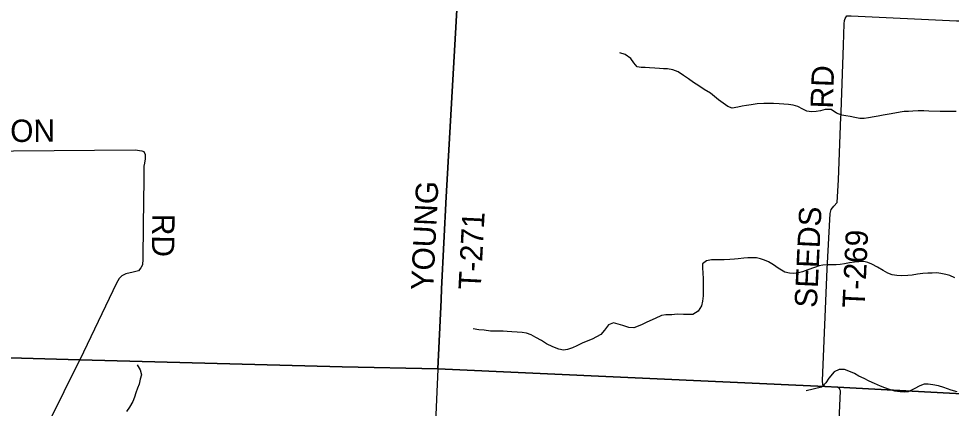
# Model space of a CAD drawing. Extents: x 114843 to 284848, y 317643 to 566895.
# Drawn here: x 166732 to 179255, y 330149 to 335383 of the extents above; entities that cross this region are included whole.
import ezdxf

# ---------------------------------------------------------------- set-up
doc = ezdxf.new("R2010")
doc.units = 0
for name, color, linetype in [('GM_X_County', 7, 'Continuous'), ('GM_X_Minor_River', 7, 'Continuous'), ('GM_X_Township', 7, 'Continuous'), ('GM_X_Township_Road', 7, 'Continuous'), ('GM_X_Township_Road_Text', 7, 'Continuous')]:
    doc.layers.add(name, color=color, linetype=linetype)

msp = doc.modelspace()

# ---------------------------------------------------------------- linework, layer by layer
at = {"layer": 'GM_X_County'}
for points in [[(181070, 330253), (177726, 330436), (177559, 330442), (172361, 330680), (171077, 330708), (167555, 330803), (166612, 330827), (164830, 330872), (164629, 330877), (164246, 330887), (163636, 330895), (163102, 330903), (159721, 330984), (157886, 331029), (151589, 331336), (151481, 331341), (151397, 331346), (149710, 331439), (149297, 331469), (137728, 332419)], [(137728, 332419), (149297, 331469), (149710, 331439), (151397, 331346), (151481, 331341), (151589, 331336), (157886, 331029), (159721, 330984), (163102, 330903), (163636, 330895), (164246, 330887), (164629, 330877), (164830, 330872), (166612, 330827), (167555, 330803), (171077, 330708), (172361, 330680), (177559, 330442), (177726, 330436), (181070, 330253)]]:
    msp.add_lwpolyline(points, dxfattribs=at)
at = {"layer": 'GM_X_Minor_River'}
for points in [[(176448, 334207), (176388, 334193), (176312, 334179), (176256, 334203), (176192, 334247), (176130, 334291), (176074, 334338), (176020, 334380), (175938, 334432), (175866, 334480), (175794, 334526), (175728, 334573), (175660, 334619), (175588, 334669), (175518, 334695), (175446, 334707), (175392, 334709), (175338, 334713), (175274, 334716), (175204, 334722), (175146, 334726), (175092, 334726), (175038, 334738), (174992, 334788), (174950, 334846), (174876, 334901), (174806, 334923)], [(179318, 334137), (179230, 334135), (179180, 334137), (179104, 334137), (178952, 334141), (178884, 334145), (178810, 334145), (178738, 334141), (178678, 334138), (178621, 334134), (178569, 334126), (178497, 334112), (178421, 334098), (178339, 334086), (178271, 334074), (178217, 334066), (178143, 334052), (178083, 334044), (178027, 334040), (177961, 334054), (177899, 334068), (177839, 334077), (177783, 334085), (177713, 334115), (177641, 334161), (177563, 334161), (177499, 334145), (177441, 334135), (177377, 334133), (177317, 334141), (177261, 334168), (177193, 334204), (177133, 334222), (177067, 334230), (177005, 334236), (176942, 334240), (176868, 334242), (176802, 334244), (176736, 334244), (176646, 334239), (176568, 334227), (176504, 334217), (176448, 334207)], [(179300, 331901), (179236, 331933), (179182, 331949), (179116, 331962), (179062, 331968), (178996, 331966), (178938, 331964), (178872, 331960), (178800, 331950), (178728, 331940), (178672, 331934), (178588, 331930), (178522, 331932), (178460, 331942), (178402, 331965), (178342, 331999), (178264, 332045), (178188, 332085), (178132, 332109), (178080, 332121), (178012, 332119), (177954, 332114), (177890, 332102), (177822, 332090), (177764, 332082), (177709, 332076), (177643, 332076), (177583, 332078), (177531, 332074), (177479, 332064), (177419, 332042), (177329, 332008), (177255, 331984), (177185, 331966), (177135, 331962), (177081, 331964), (177019, 331980), (176929, 332033), (176867, 332075), (176799, 332117), (176747, 332139), (176693, 332159), (176639, 332169), (176585, 332172), (176523, 332170), (176469, 332166), (176395, 332158), (176345, 332152), (176281, 332148), (176203, 332142), (176147, 332144), (176088, 332146), (176036, 332142), (175966, 332130), (175916, 332092), (175914, 332030), (175918, 331968), (175922, 331890), (175924, 331820), (175922, 331737), (175922, 331661), (175913, 331591), (175901, 331527), (175857, 331453), (175783, 331411)], [(175783, 331411), (175709, 331409), (175657, 331411), (175575, 331413), (175501, 331407), (175421, 331403), (175363, 331395), (175277, 331357), (175209, 331325), (175158, 331303), (175104, 331277), (175052, 331253), (174990, 331229), (174924, 331237), (174846, 331260), (174718, 331296), (174652, 331270), (174598, 331198), (174548, 331142), (174492, 331108), (174432, 331080), (174376, 331058), (174297, 331024), (174229, 330988), (174167, 330960), (174101, 330938), (174049, 330930), (173987, 330944), (173905, 330976), (173819, 331018), (173751, 331059), (173677, 331101), (173613, 331135), (173551, 331161), (173493, 331167), (173427, 331173), (173355, 331177), (173291, 331181), (173237, 331184), (173175, 331186), (173119, 331186), (173069, 331188), (172983, 331198), (172909, 331206), (172833, 331216)], [(168324, 330733), (168364, 330665), (168380, 330600), (168366, 330540), (168349, 330476), (168327, 330422), (168307, 330356), (168287, 330300), (168267, 330240), (168219, 330163), (168181, 330109)], [(179332, 330373), (179252, 330392), (179156, 330430), (179082, 330450), (179006, 330466), (178942, 330474), (178890, 330472), (178830, 330450), (178754, 330410), (178675, 330372), (178625, 330368), (178567, 330370), (178495, 330381), (178423, 330403), (178363, 330425), (178305, 330449), (178223, 330483), (178153, 330515), (178085, 330548), (178015, 330582), (177953, 330616), (177881, 330650), (177821, 330670), (177751, 330672), (177681, 330638), (177611, 330556), (177569, 330492), (177513, 330436), (177307, 330386)]]:
    msp.add_lwpolyline(points, dxfattribs=at)
at = {"layer": 'GM_X_Township'}
for points in [[(172451, 346337), (172681, 344992), (172863, 343417), (172954, 342875), (172978, 342712), (172778, 338411), (172759, 338018), (172753, 337899), (172727, 337514), (172727, 337511), (172677, 336606), (172473, 332991), (172412, 331756), (172407, 331608), (172361, 330680), (171077, 330708), (167555, 330803), (166612, 330827)], [(181070, 330253), (177726, 330436), (177559, 330442), (172361, 330680), (172407, 331608), (172412, 331756), (172473, 332991), (172677, 336606), (172727, 337511), (172727, 337514), (172753, 337899), (172759, 338018), (172778, 338411), (172978, 342712), (172954, 342875), (172863, 343417), (172681, 344992), (172451, 346337)], [(166612, 330827), (167555, 330803), (171077, 330708), (172361, 330680), (177559, 330442), (177726, 330436), (181070, 330253)]]:
    msp.add_lwpolyline(points, dxfattribs=at)
at = {"layer": 'GM_X_Township_Road'}
for p, q in [((172362, 330677), (172410, 331675)), ((172362, 330677), (172265, 328548)), ((177727, 330433), (177561, 330440))]:
    msp.add_line(p, q, dxfattribs=at)
for points in [[(177774, 334097), (177775, 334129), (177807, 335026), (177815, 335315), (177819, 335357), (177831, 335387), (177852, 335419), (177912, 335422), (179323, 335354), (179365, 335353), (179391, 335367), (179395, 335397), (179461, 337466)], [(172410, 331675), (172414, 331754), (172474, 332988), (172679, 336603), (172694, 336881)], [(177561, 330440), (177531, 330466), (177524, 330523), (177589, 332018), (177629, 332765), (177640, 332819), (177678, 332865), (177723, 332916), (177739, 333219), (177772, 334065), (177774, 334097)], [(165027, 333593), (168298, 333619), (168387, 333609), (168411, 333597), (168433, 333559), (168433, 333499), (168423, 333441), (168414, 333403), (168414, 333372)], [(168414, 333372), (168414, 333346), (168412, 333228), (168406, 332613), (168400, 332152), (168394, 332076), (168372, 332036), (168340, 331994), (168268, 331980), (168172, 331956), (168116, 331930), (168080, 331892), (168046, 331830), (167556, 330800)], [(166485, 328625), (166511, 328693), (167556, 330800)], [(177585, 326491), (177604, 326631), (177664, 327542), (177668, 327680), (177702, 328896), (177765, 330384), (177757, 330404), (177752, 330414), (177727, 330433)]]:
    msp.add_lwpolyline(points, dxfattribs=at)

# ---------------------------------------------------------------- texts
at = {"layer": 'GM_X_Township_Road_Text'}
for s, rotation, p in [('RD', 87.944, (177663, 334172)), ('DENTON', 0.4125, (165528, 333718)), ('YOUNG', 87.1904, (172298, 331727)), ('T-271', 87.0478, (172936, 331736)), ('SEEDS', 87.2702, (177449, 331495)), ('RD', 269.4267, (168527, 332763)), ('T-269', 87.3563, (178091, 331493))]:
    msp.add_text(s, height=300, rotation=rotation, dxfattribs=at).set_placement(p)

doc.saveas('drawing.dxf')
